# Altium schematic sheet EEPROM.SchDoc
size A
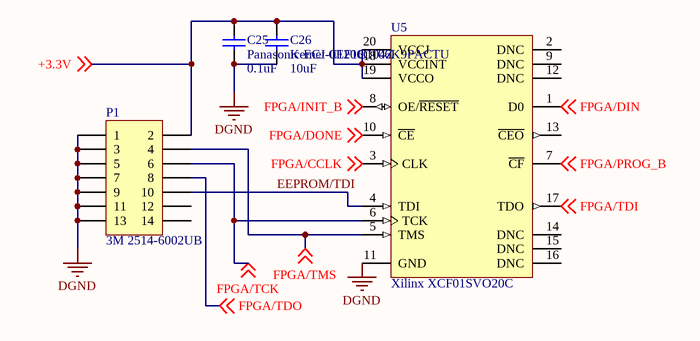
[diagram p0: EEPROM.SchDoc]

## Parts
C25  Panasonic ECJ-0EF1C104Z  value 0.1uF  [0402]
C26  Kemet C1206C106K9PACTU  value 10uF  [C1206]
P1  3M 2514-6002UB  [Xilinx Header]
U5  Xilinx XCF01SVO20C  [VO20_N]

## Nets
DGND: C25.1 C26.1 P1.1 P1.3 P1.5 P1.7 P1.9 P1.11 P1.13 U5.11(GND)
+3.3V: C25.2 C26.2 P1.2 U5.18(VCCINT) U5.19(VCCO) U5.20(VCCJ) ; off-sheet +3.3V
EEPROM/TDI: P1.10 U5.4(TDI)
FPGA/CCLK: U5.3(CLK) ; off-sheet FPGA/CCLK
FPGA/DIN: U5.1(D0) ; off-sheet FPGA/DIN
FPGA/DONE: U5.10(~{CE}) ; off-sheet FPGA/DONE
FPGA/INIT_B: U5.8(OE/~{RESET}) ; off-sheet FPGA/INIT_B
FPGA/PROG_B: U5.7(~{CF}) ; off-sheet FPGA/PROG_B
FPGA/TCK: P1.6 U5.6(TCK) ; off-sheet FPGA/TCK
FPGA/TDI: U5.17(TDO) ; off-sheet FPGA/TDI
FPGA/TDO: P1.8 ; off-sheet FPGA/TDO
FPGA/TMS: P1.4 U5.5(TMS) ; off-sheet FPGA/TMS

Not connected (* = marked no-connect by the designer): P1 12 14; U5 2(DNC) 9(DNC) 12(DNC) 13(~{CEO}) 14(DNC) 15(DNC) 16(DNC)

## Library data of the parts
C25 C26 = Cap: Capacitor
P1 = Header 7X2: Header, 7-Pin, Dual row
U5 = XCF01SVO20C: XCF00S Series, Platform Flash In-System Programmable Configuration 3.3V PROM, 20-Pin TSOP, 1-Megabit, Commercial Grade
